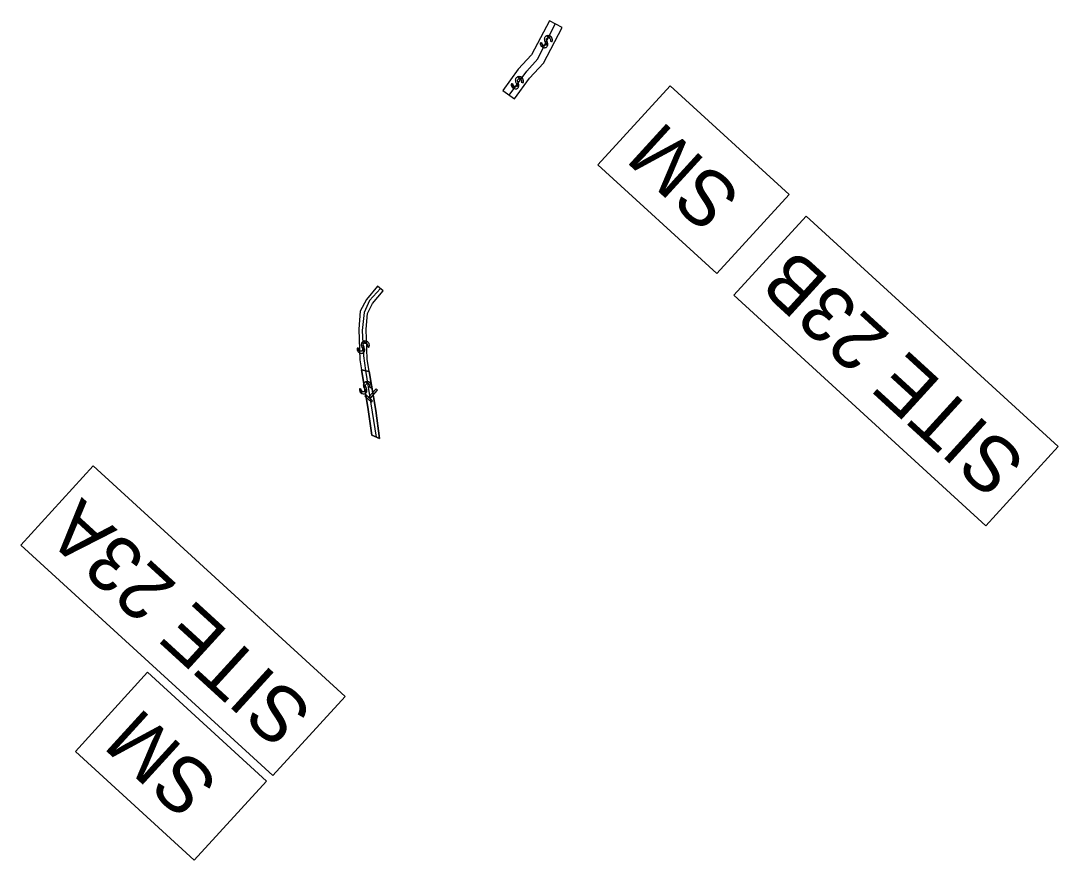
# Model space of a CAD drawing. Extents: x 474218 to 481634, y 484357 to 504997.
# Drawn here: x 476470.4 to 476752, y 500473.4 to 500701.1 of the extents above; entities that cross this region are included whole.
import ezdxf

# ---------------------------------------------------------------- set-up
doc = ezdxf.new("R2010")
doc.units = 0
for name, color, linetype in [('Exist Hydro Jurisdictional Stream or Body of Water', 7, 'Continuous'), ('Old_Level_29', 7, 'Continuous'), ('Prop Earthen Structure Impacts In Surface Waters Hatching CELL', 7, 'Continuous'), ('Prop Grid Mask', 7, 'Continuous'), ('Scratch_Level_4', 7, 'Continuous'), ('Temp Earthen Structure Impacts In Surface Waters Hatching CELL', 7, 'Continuous')]:
    doc.layers.add(name, color=color, linetype=linetype)

msp = doc.modelspace()

# ---------------------------------------------------------------- linework, layer by layer
at = {"layer": 'Exist Hydro Jurisdictional Stream or Body of Water'}
for points in [[(476659.33, 500632.47), (476627.05, 500661.96), (476646.67, 500683.43), (476678.95, 500653.94)], [(476517.54, 500473.4), (476485.26, 500502.89), (476504.88, 500524.36), (476537.16, 500494.87)]]:
    msp.add_lwpolyline(points, close=True, dxfattribs=at)
at = {"layer": 'Old_Level_29'}
for points in [[(476732.35, 500564.12), (476663.96, 500626.62), (476683.58, 500648.1), (476751.98, 500585.6)], [(476538.84, 500496.37), (476470.44, 500558.87), (476490.07, 500580.34), (476558.46, 500517.84)]]:
    msp.add_lwpolyline(points, close=True, dxfattribs=at)
at = {"layer": 'Prop Earthen Structure Impacts In Surface Waters Hatching CELL'}
for p, q in [((476617.39, 500699.23), (476613.93, 500701.05)), ((476601.27, 500682.18), (476604.44, 500679.88)), ((476568.81, 500627.79), (476567.28, 500629.08)), ((476562.9, 500606.39), (476565.01, 500605.93))]:
    msp.add_line(p, q, dxfattribs=at)
for points in [[(476613.93, 500701.05), (476609.06, 500691.83), (476605.44, 500687.94), (476601.27, 500682.18)], [(476604.44, 500679.88), (476608.47, 500685.45), (476612.29, 500689.54), (476617.39, 500699.23)], [(476567.28, 500629.08), (476564.23, 500625.47), (476562.55, 500622.27), (476562.18, 500617.43), (476562.46, 500609.07), (476562.9, 500606.39)], [(476565.01, 500605.93), (476564.45, 500609.26), (476564.18, 500617.39), (476564.51, 500621.71), (476565.9, 500624.34), (476568.81, 500627.79)]]:
    msp.add_lwpolyline(points, dxfattribs=at)
for points in [[(476613.79, 500696.47), (476613.98, 500696.35), (476613.25, 500697.01), (476613.21, 500697), (476613.2, 500697), (476613.19, 500697), (476613.11, 500696.98), (476613.09, 500696.96), (476613.07, 500696.95), (476612.99, 500696.89), (476612.95, 500696.86), (476612.92, 500696.84), (476612.81, 500696.76), (476612.76, 500696.69), (476612.64, 500696.53), (476612.59, 500696.46), (476612.57, 500696.38), (476612.54, 500696.23), (476612.54, 500696.23), (476612.51, 500696.12), (476612.53, 500696), (476612.57, 500695.73), (476612.6, 500695.65), (476612.72, 500695.32), (476612.79, 500695.16), (476613.49, 500694.52), (476613.48, 500694.63), (476613.47, 500694.86), (476613.45, 500694.93), (476613.35, 500695.25), (476613.3, 500695.4), (476613.21, 500695.62), (476613.11, 500695.89), (476613.1, 500695.99), (476613.1, 500696.11), (476613.19, 500696.3), (476613.25, 500696.36), (476613.35, 500696.45), (476613.39, 500696.46), (476613.43, 500696.48), (476613.54, 500696.52), (476613.58, 500696.51), (476613.63, 500696.5), (476613.76, 500696.48), (476613.77, 500696.48)], [(476614.65, 500696.34), (476614.35, 500696.72), (476613.93, 500697), (476613.92, 500697), (476613.53, 500697.07), (476613.48, 500697.07), (476613.25, 500697.01), (476613.98, 500696.35), (476614.14, 500696.14), (476614.15, 500696.14), (476614.15, 500696.12), (476614.21, 500695.98), (476614.23, 500695.92), (476614.22, 500695.89), (476614.22, 500695.76), (476614.21, 500695.7), (476614.2, 500695.67), (476614.15, 500695.54), (476614.45, 500695.44), (476614.53, 500695.42), (476614.63, 500695.39), (476614.67, 500695.48), (476614.68, 500695.5), (476614.69, 500695.53), (476614.72, 500695.6), (476614.73, 500695.61), (476614.73, 500695.61), (476614.73, 500695.66), (476614.76, 500695.9), (476614.77, 500695.94), (476614.65, 500696.33)], [(476613.31, 500694.12), (476613.39, 500694.22), (476612.9, 500694.67), (476612.87, 500694.52), (476612.75, 500694.37), (476612.74, 500694.36), (476612.7, 500694.34), (476612.57, 500694.28), (476612.51, 500694.28), (476612.42, 500694.28), (476612.38, 500694.28), (476612.35, 500694.3), (476612.27, 500694.34), (476612.17, 500694.39), (476611.45, 500695.05), (476611.43, 500694.99), (476611.43, 500694.75), (476611.43, 500694.7), (476611.54, 500694.38), (476612.19, 500693.79), (476612.48, 500693.73), (476612.56, 500693.72), (476612.77, 500693.76), (476612.85, 500693.77), (476612.88, 500693.78), (476612.91, 500693.78), (476612.92, 500693.79), (476612.94, 500693.8), (476612.99, 500693.84), (476613.03, 500693.86), (476613.14, 500693.93), (476613.18, 500693.96), (476613.19, 500693.96)], [(476611.95, 500694.85), (476611.96, 500695.01), (476611.69, 500695.08), (476611.6, 500695.11), (476611.47, 500695.14), (476611.47, 500695.11), (476611.46, 500695.11), (476611.46, 500695.08), (476611.45, 500695.05), (476612.17, 500694.39), (476612, 500694.58), (476611.99, 500694.62), (476611.99, 500694.64), (476611.97, 500694.69), (476611.94, 500694.79)], [(476612.15, 500693.82), (476612.19, 500693.79), (476611.54, 500694.38), (476611.55, 500694.37), (476611.83, 500694.03), (476611.83, 500694.03)], [(476613.46, 500694.44), (476613.49, 500694.52), (476612.79, 500695.16), (476612.87, 500694.99), (476612.92, 500694.74), (476612.9, 500694.67), (476613.39, 500694.22), (476613.41, 500694.28)], [(476605.92, 500685.31), (476606.11, 500685.19), (476605.38, 500685.86), (476605.34, 500685.84), (476605.33, 500685.84), (476605.32, 500685.84), (476605.24, 500685.82), (476605.22, 500685.8), (476605.2, 500685.79), (476605.12, 500685.73), (476605.08, 500685.7), (476605.05, 500685.68), (476604.94, 500685.6), (476604.89, 500685.54), (476604.77, 500685.37), (476604.72, 500685.3), (476604.7, 500685.23), (476604.67, 500685.08), (476604.67, 500685.08), (476604.64, 500684.96), (476604.66, 500684.85), (476604.7, 500684.57), (476604.73, 500684.5), (476604.85, 500684.17), (476604.93, 500684), (476605.62, 500683.37), (476605.62, 500683.47), (476605.61, 500683.7), (476605.58, 500683.77), (476605.49, 500684.09), (476605.43, 500684.24), (476605.34, 500684.46), (476605.24, 500684.74), (476605.24, 500684.83), (476605.23, 500684.96), (476605.32, 500685.15), (476605.38, 500685.2), (476605.48, 500685.29), (476605.52, 500685.3), (476605.56, 500685.32), (476605.67, 500685.36), (476605.71, 500685.35), (476605.76, 500685.34), (476605.89, 500685.32), (476605.91, 500685.32)], [(476606.78, 500685.18), (476606.48, 500685.56), (476606.06, 500685.84), (476606.06, 500685.84), (476605.66, 500685.91), (476605.61, 500685.92), (476605.38, 500685.86), (476606.11, 500685.19), (476606.28, 500684.99), (476606.28, 500684.98), (476606.29, 500684.96), (476606.34, 500684.82), (476606.36, 500684.76), (476606.36, 500684.74), (476606.35, 500684.6), (476606.35, 500684.55), (476606.33, 500684.51), (476606.28, 500684.38), (476606.58, 500684.28), (476606.66, 500684.26), (476606.76, 500684.23), (476606.8, 500684.33), (476606.81, 500684.35), (476606.83, 500684.37), (476606.86, 500684.44), (476606.86, 500684.45), (476606.86, 500684.46), (476606.86, 500684.5), (476606.89, 500684.75), (476606.9, 500684.78), (476606.79, 500685.17)], [(476605.45, 500682.96), (476605.53, 500683.06), (476605.03, 500683.51), (476605, 500683.36), (476604.88, 500683.21), (476604.87, 500683.2), (476604.83, 500683.18), (476604.71, 500683.12), (476604.64, 500683.12), (476604.55, 500683.12), (476604.51, 500683.13), (476604.48, 500683.14), (476604.4, 500683.18), (476604.3, 500683.24), (476603.58, 500683.89), (476603.56, 500683.83), (476603.56, 500683.59), (476603.56, 500683.54), (476603.68, 500683.23), (476604.32, 500682.64), (476604.61, 500682.57), (476604.69, 500682.56), (476604.91, 500682.6), (476604.98, 500682.61), (476605.02, 500682.62), (476605.04, 500682.63), (476605.05, 500682.63), (476605.07, 500682.65), (476605.12, 500682.68), (476605.16, 500682.7), (476605.27, 500682.77), (476605.31, 500682.8), (476605.32, 500682.81)], [(476604.08, 500683.69), (476604.09, 500683.86), (476603.82, 500683.93), (476603.73, 500683.95), (476603.61, 500683.99), (476603.6, 500683.96), (476603.6, 500683.95), (476603.59, 500683.93), (476603.58, 500683.89), (476604.3, 500683.24), (476604.14, 500683.43), (476604.12, 500683.47), (476604.12, 500683.48), (476604.11, 500683.53), (476604.08, 500683.64)], [(476604.28, 500682.66), (476604.32, 500682.64), (476603.68, 500683.23), (476603.68, 500683.21), (476603.96, 500682.87), (476603.96, 500682.87)], [(476605.6, 500683.29), (476605.62, 500683.37), (476604.93, 500684), (476605, 500683.83), (476605.05, 500683.58), (476605.03, 500683.51), (476605.53, 500683.06), (476605.55, 500683.13)], [(476563.61, 500611.27), (476563.69, 500611.37), (476563.2, 500611.82), (476563.17, 500611.67), (476563.04, 500611.52), (476563.04, 500611.51), (476562.99, 500611.49), (476562.87, 500611.42), (476562.8, 500611.43), (476562.71, 500611.43), (476562.67, 500611.43), (476562.65, 500611.44), (476562.57, 500611.49), (476562.46, 500611.54), (476561.74, 500612.2), (476561.72, 500612.14), (476561.72, 500611.9), (476561.72, 500611.85), (476561.84, 500611.53), (476562.48, 500610.94), (476562.78, 500610.88), (476562.86, 500610.86), (476563.07, 500610.91), (476563.14, 500610.92), (476563.18, 500610.93), (476563.21, 500610.93), (476563.21, 500610.94), (476563.24, 500610.95), (476563.29, 500610.98), (476563.33, 500611.01), (476563.44, 500611.08), (476563.48, 500611.11), (476563.49, 500611.11)], [(476562.24, 500612), (476562.25, 500612.16), (476561.99, 500612.23), (476561.89, 500612.26), (476561.77, 500612.29), (476561.76, 500612.26), (476561.76, 500612.26), (476561.75, 500612.23), (476561.74, 500612.2), (476562.46, 500611.54), (476562.3, 500611.73), (476562.29, 500611.77), (476562.28, 500611.78), (476562.27, 500611.83), (476562.24, 500611.94)], [(476564.08, 500613.62), (476564.27, 500613.5), (476563.54, 500614.16), (476563.5, 500614.15), (476563.5, 500614.15), (476563.49, 500614.15), (476563.41, 500614.13), (476563.38, 500614.11), (476563.37, 500614.1), (476563.28, 500614.03), (476563.24, 500614.01), (476563.21, 500613.99), (476563.1, 500613.91), (476563.05, 500613.84), (476562.93, 500613.68), (476562.88, 500613.61), (476562.87, 500613.53), (476562.83, 500613.38), (476562.83, 500613.38), (476562.8, 500613.26), (476562.82, 500613.15), (476562.87, 500612.88), (476562.9, 500612.8), (476563.02, 500612.47), (476563.09, 500612.31), (476563.78, 500611.67), (476563.78, 500611.78), (476563.77, 500612.01), (476563.75, 500612.08), (476563.65, 500612.4), (476563.59, 500612.54), (476563.5, 500612.77), (476563.4, 500613.04), (476563.4, 500613.14), (476563.39, 500613.26), (476563.48, 500613.45), (476563.54, 500613.51), (476563.64, 500613.59), (476563.68, 500613.61), (476563.73, 500613.63), (476563.84, 500613.67), (476563.88, 500613.66), (476563.93, 500613.65), (476564.05, 500613.63), (476564.07, 500613.63)], [(476563.76, 500611.59), (476563.78, 500611.67), (476563.09, 500612.31), (476563.16, 500612.14), (476563.21, 500611.89), (476563.2, 500611.82), (476563.69, 500611.37), (476563.71, 500611.43)], [(476564.95, 500613.49), (476564.64, 500613.87), (476564.22, 500614.15), (476564.22, 500614.15), (476563.82, 500614.21), (476563.78, 500614.22), (476563.54, 500614.16), (476564.27, 500613.5), (476564.44, 500613.29), (476564.44, 500613.29), (476564.45, 500613.27), (476564.5, 500613.13), (476564.52, 500613.07), (476564.52, 500613.04), (476564.51, 500612.91), (476564.51, 500612.85), (476564.5, 500612.82), (476564.45, 500612.69), (476564.74, 500612.59), (476564.82, 500612.57), (476564.92, 500612.53), (476564.97, 500612.63), (476564.98, 500612.65), (476564.99, 500612.68), (476565.02, 500612.75), (476565.02, 500612.76), (476565.02, 500612.76), (476565.03, 500612.81), (476565.06, 500613.05), (476565.06, 500613.08), (476564.95, 500613.48)], [(476562.45, 500610.97), (476562.48, 500610.94), (476561.84, 500611.53), (476561.84, 500611.52), (476562.12, 500611.18), (476562.12, 500611.18)]]:
    msp.add_lwpolyline(points, close=True, dxfattribs=at)
at = {"layer": 'Prop Grid Mask'}
for points in [[(476678.95, 500653.94), (476646.67, 500683.43), (476627.05, 500661.96), (476659.33, 500632.47)], [(476751.98, 500585.6), (476683.58, 500648.1), (476663.96, 500626.62), (476732.35, 500564.12)], [(476558.46, 500517.84), (476490.07, 500580.34), (476470.44, 500558.87), (476538.84, 500496.37)], [(476537.16, 500494.87), (476504.88, 500524.36), (476485.26, 500502.89), (476517.54, 500473.4)]]:
    msp.add_lwpolyline(points, close=True, dxfattribs=at)
at = {"layer": 'Scratch_Level_4'}
for p, q in [((476617.39, 500699.23), (476613.93, 500701.05)), ((476601.27, 500682.18), (476604.44, 500679.88)), ((476568.81, 500627.79), (476567.28, 500629.08)), ((476562.9, 500606.39), (476565.01, 500605.93)), ((476562.9, 500606.39), (476565.01, 500605.93)), ((476563.95, 500606.21), (476566.91, 500588.13))]:
    msp.add_line(p, q, dxfattribs=at)
for points in [[(476613.93, 500701.05), (476609.06, 500691.83), (476605.44, 500687.94), (476601.27, 500682.18)], [(476603.02, 500680.92), (476607.76, 500687.35), (476610.79, 500690.75), (476615.5, 500700.22)], [(476604.44, 500679.88), (476608.47, 500685.45), (476612.29, 500689.54), (476617.39, 500699.23)], [(476567.28, 500629.08), (476564.23, 500625.47), (476562.55, 500622.27), (476562.18, 500617.43), (476562.46, 500609.07), (476562.9, 500606.39)], [(476568.07, 500628.43), (476565.08, 500625.15), (476563.61, 500621.94), (476563.12, 500617.06), (476563.48, 500610.16), (476563.95, 500606.21)], [(476565.01, 500605.93), (476564.45, 500609.26), (476564.18, 500617.39), (476564.51, 500621.71), (476565.9, 500624.34), (476568.81, 500627.79)], [(476564.61, 500596.22), (476562.9, 500606.39)], [(476565.01, 500605.93), (476566.78, 500595.39)], [(476566.78, 500595.39), (476567.81, 500587.75), (476565.67, 500588.64), (476564.61, 500596.22)]]:
    msp.add_lwpolyline(points, dxfattribs=at)
at = {"layer": 'Temp Earthen Structure Impacts In Surface Waters Hatching CELL'}
for p, q in [((476565.01, 500605.93), (476562.9, 500606.39)), ((476562.9, 500606.39), (476564.61, 500596.22)), ((476566.78, 500595.39), (476565.01, 500605.93))]:
    msp.add_line(p, q, dxfattribs=at)
for points in [[(476564.21, 500600.26), (476564.29, 500600.36), (476563.8, 500600.81), (476563.76, 500600.66), (476563.64, 500600.51), (476563.63, 500600.5), (476563.59, 500600.47), (476563.47, 500600.41), (476563.4, 500600.42), (476563.31, 500600.42), (476563.27, 500600.42), (476563.24, 500600.43), (476563.16, 500600.48), (476563.06, 500600.53), (476562.34, 500601.19), (476562.32, 500601.13), (476562.32, 500600.89), (476562.32, 500600.83), (476562.44, 500600.52), (476563.08, 500599.93), (476563.37, 500599.87), (476563.45, 500599.85), (476563.67, 500599.89), (476563.74, 500599.91), (476563.78, 500599.91), (476563.8, 500599.92), (476563.81, 500599.92), (476563.83, 500599.94), (476563.89, 500599.97), (476563.92, 500600), (476564.03, 500600.07), (476564.07, 500600.09), (476564.09, 500600.1)], [(476562.84, 500600.99), (476562.85, 500601.15), (476562.58, 500601.22), (476562.49, 500601.25), (476562.37, 500601.28), (476562.36, 500601.25), (476562.36, 500601.24), (476562.35, 500601.22), (476562.34, 500601.19), (476563.06, 500600.53), (476562.9, 500600.72), (476562.89, 500600.76), (476562.88, 500600.77), (476562.87, 500600.82), (476562.84, 500600.93)], [(476564.68, 500602.61), (476564.87, 500602.49), (476564.14, 500603.15), (476564.1, 500603.14), (476564.1, 500603.14), (476564.09, 500603.13), (476564, 500603.11), (476563.98, 500603.1), (476563.96, 500603.08), (476563.88, 500603.02), (476563.84, 500603), (476563.81, 500602.98), (476563.7, 500602.9), (476563.65, 500602.83), (476563.53, 500602.67), (476563.48, 500602.6), (476563.46, 500602.52), (476563.43, 500602.37), (476563.43, 500602.37), (476563.4, 500602.25), (476563.42, 500602.14), (476563.47, 500601.87), (476563.49, 500601.79), (476563.62, 500601.46), (476563.69, 500601.3), (476564.38, 500600.66), (476564.38, 500600.76), (476564.37, 500600.99), (476564.35, 500601.06), (476564.25, 500601.39), (476564.19, 500601.53), (476564.1, 500601.76), (476564, 500602.03), (476564, 500602.13), (476563.99, 500602.25), (476564.08, 500602.44), (476564.14, 500602.49), (476564.24, 500602.58), (476564.28, 500602.6), (476564.33, 500602.61), (476564.44, 500602.65), (476564.47, 500602.65), (476564.52, 500602.64), (476564.65, 500602.62), (476564.67, 500602.62)], [(476564.36, 500600.58), (476564.38, 500600.66), (476563.69, 500601.3), (476563.76, 500601.13), (476563.81, 500600.87), (476563.8, 500600.81), (476564.29, 500600.36), (476564.31, 500600.42)], [(476565.54, 500602.47), (476565.24, 500602.86), (476564.82, 500603.14), (476564.82, 500603.14), (476564.42, 500603.2), (476564.37, 500603.21), (476564.14, 500603.15), (476564.87, 500602.49), (476565.04, 500602.28), (476565.04, 500602.28), (476565.05, 500602.26), (476565.1, 500602.11), (476565.12, 500602.06), (476565.12, 500602.03), (476565.11, 500601.9), (476565.11, 500601.84), (476565.09, 500601.8), (476565.04, 500601.67), (476565.34, 500601.58), (476565.42, 500601.55), (476565.52, 500601.52), (476565.57, 500601.62), (476565.57, 500601.64), (476565.59, 500601.67), (476565.62, 500601.74), (476565.62, 500601.75), (476565.62, 500601.75), (476565.62, 500601.8), (476565.65, 500602.04), (476565.66, 500602.07), (476565.55, 500602.47)], [(476565.24, 500598.64), (476567.28, 500600.87), (476566.86, 500601.25), (476564.82, 500599.02)], [(476563.04, 500599.96), (476563.08, 500599.93), (476562.44, 500600.52), (476562.44, 500600.51), (476562.72, 500600.17), (476562.72, 500600.17)], [(476565.6, 500597.65), (476565.93, 500598.01), (476564.13, 500599.65), (476563.8, 500599.29)]]:
    msp.add_lwpolyline(points, close=True, dxfattribs=at)
msp.add_lwpolyline([(476564.61, 500596.22), (476565.67, 500588.64), (476567.81, 500587.75), (476566.78, 500595.39)], dxfattribs=at)

# ---------------------------------------------------------------- texts
at = {"layer": 'Exist Hydro Jurisdictional Stream or Body of Water'}
for p in [(476666.55, 500653.92), (476524.77, 500494.85)]:
    msp.add_text('SM', height=15, rotation=137.5803, dxfattribs=at).set_placement(p)
at = {"layer": 'Old_Level_29'}
for s, p in [('SITE 23B', (476743.8, 500581.82)), ('SITE 23A', (476550.29, 500514.06))]:
    msp.add_text(s, height=15, rotation=137.5803, dxfattribs=at).set_placement(p)

doc.saveas('drawing.dxf')
